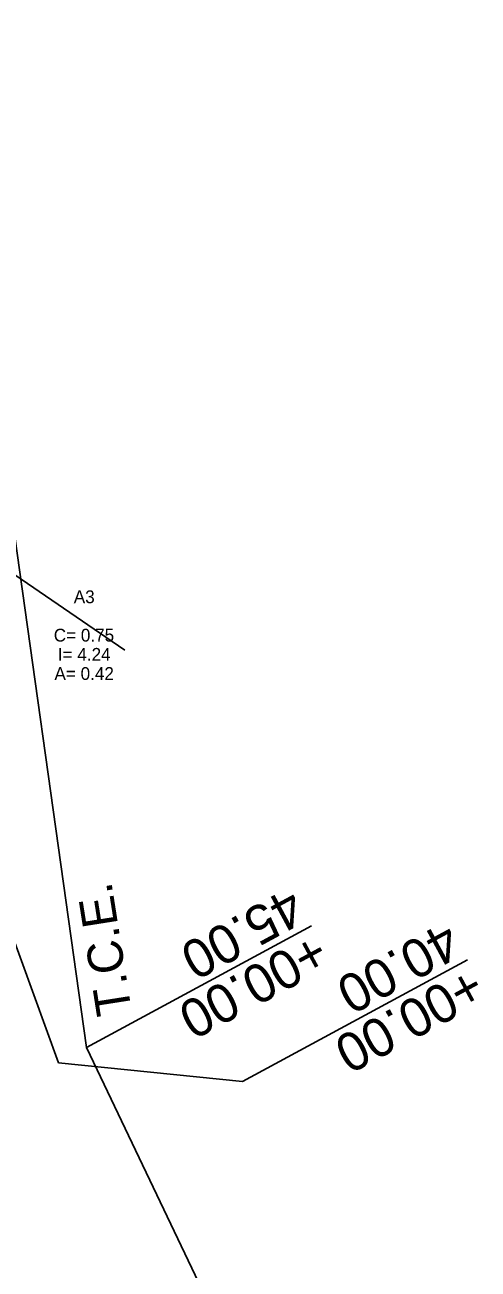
# Model space of a CAD drawing. Extents: x 1627557 to 1636561, y 783843 to 794002.
# Drawn here: x 1628299.3 to 1628370.2, y 784515.8 to 784710.3 of the extents above; entities that cross this region are included whole.
import ezdxf

# ---------------------------------------------------------------- set-up
doc = ezdxf.new("R2010")
doc.units = 0
for name, color, linetype in [('R_Drainage_Areas_Annot', 7, 'Continuous'), ('R_ROW', 7, 'Continuous'), ('R_ROW Annot', 7, 'Continuous'), ('R_Temp Const Easement', 7, 'Continuous'), ('R_Temp Const Easement Annot', 7, 'Continuous'), ('R_Temp Easement Annot', 7, 'Continuous')]:
    doc.layers.add(name, color=color, linetype=linetype)

msp = doc.modelspace()

# ---------------------------------------------------------------- linework, layer by layer
at = {"layer": 'R_ROW'}
msp.add_line((1628304.54, 784548.02), (1628269.98, 784643.22), dxfattribs=at)
at = {"layer": 'R_ROW Annot'}
for p, q in [((1628314.94, 784612.53), (1628269.98, 784643.22)), ((1628333.34, 784545.06), (1628304.54, 784548.02))]:
    msp.add_line(p, q, dxfattribs=at)
msp.add_lwpolyline([(1628333.34, 784545.06), (1628368.52, 784564.09)], dxfattribs=at)
at = {"layer": 'R_Temp Const Easement'}
for p, q in [((1628308.94, 784550.4), (1628279.18, 784762.14)), ((1628352.13, 784460.07), (1628308.94, 784550.4))]:
    msp.add_line(p, q, dxfattribs=at)
at = {"layer": 'R_Temp Easement Annot'}
msp.add_lwpolyline([(1628308.94, 784550.4), (1628344.12, 784569.43)], dxfattribs=at)

# ---------------------------------------------------------------- texts
at = {"layer": 'R_Drainage_Areas_Annot'}
for s, p in [('A3', (1628306.95, 784619.86)), ('C= 0.75', (1628303.82, 784613.86)), ('I= 4.24', (1628304.46, 784610.86)), ('A= 0.42', (1628303.93, 784607.86))]:
    msp.add_text(s, height=2, dxfattribs=at).set_placement(p)
at = {"layer": 'R_ROW Annot'}
for s, p in [('40.00', (1628365.19, 784570.25)), ('+00.00', (1628368.99, 784563.21))]:
    msp.add_text(s, height=6, rotation=208.4133, dxfattribs=at).set_placement(p)
at = {"layer": 'R_Temp Const Easement Annot'}
msp.add_text('T.C.E.', height=5.5, rotation=98.9552, dxfattribs=at).set_placement((1628316.05, 784555.87))
at = {"layer": 'R_Temp Easement Annot'}
for s, p in [('45.00', (1628340.79, 784575.59)), ('+00.00', (1628344.6, 784568.55))]:
    msp.add_text(s, height=6, rotation=208.4133, dxfattribs=at).set_placement(p)

doc.saveas('drawing.dxf')
